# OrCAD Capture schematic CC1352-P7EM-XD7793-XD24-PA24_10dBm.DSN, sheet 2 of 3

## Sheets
2 CC1352-P7EM-XD7793-XD24-PA24_10: size A3
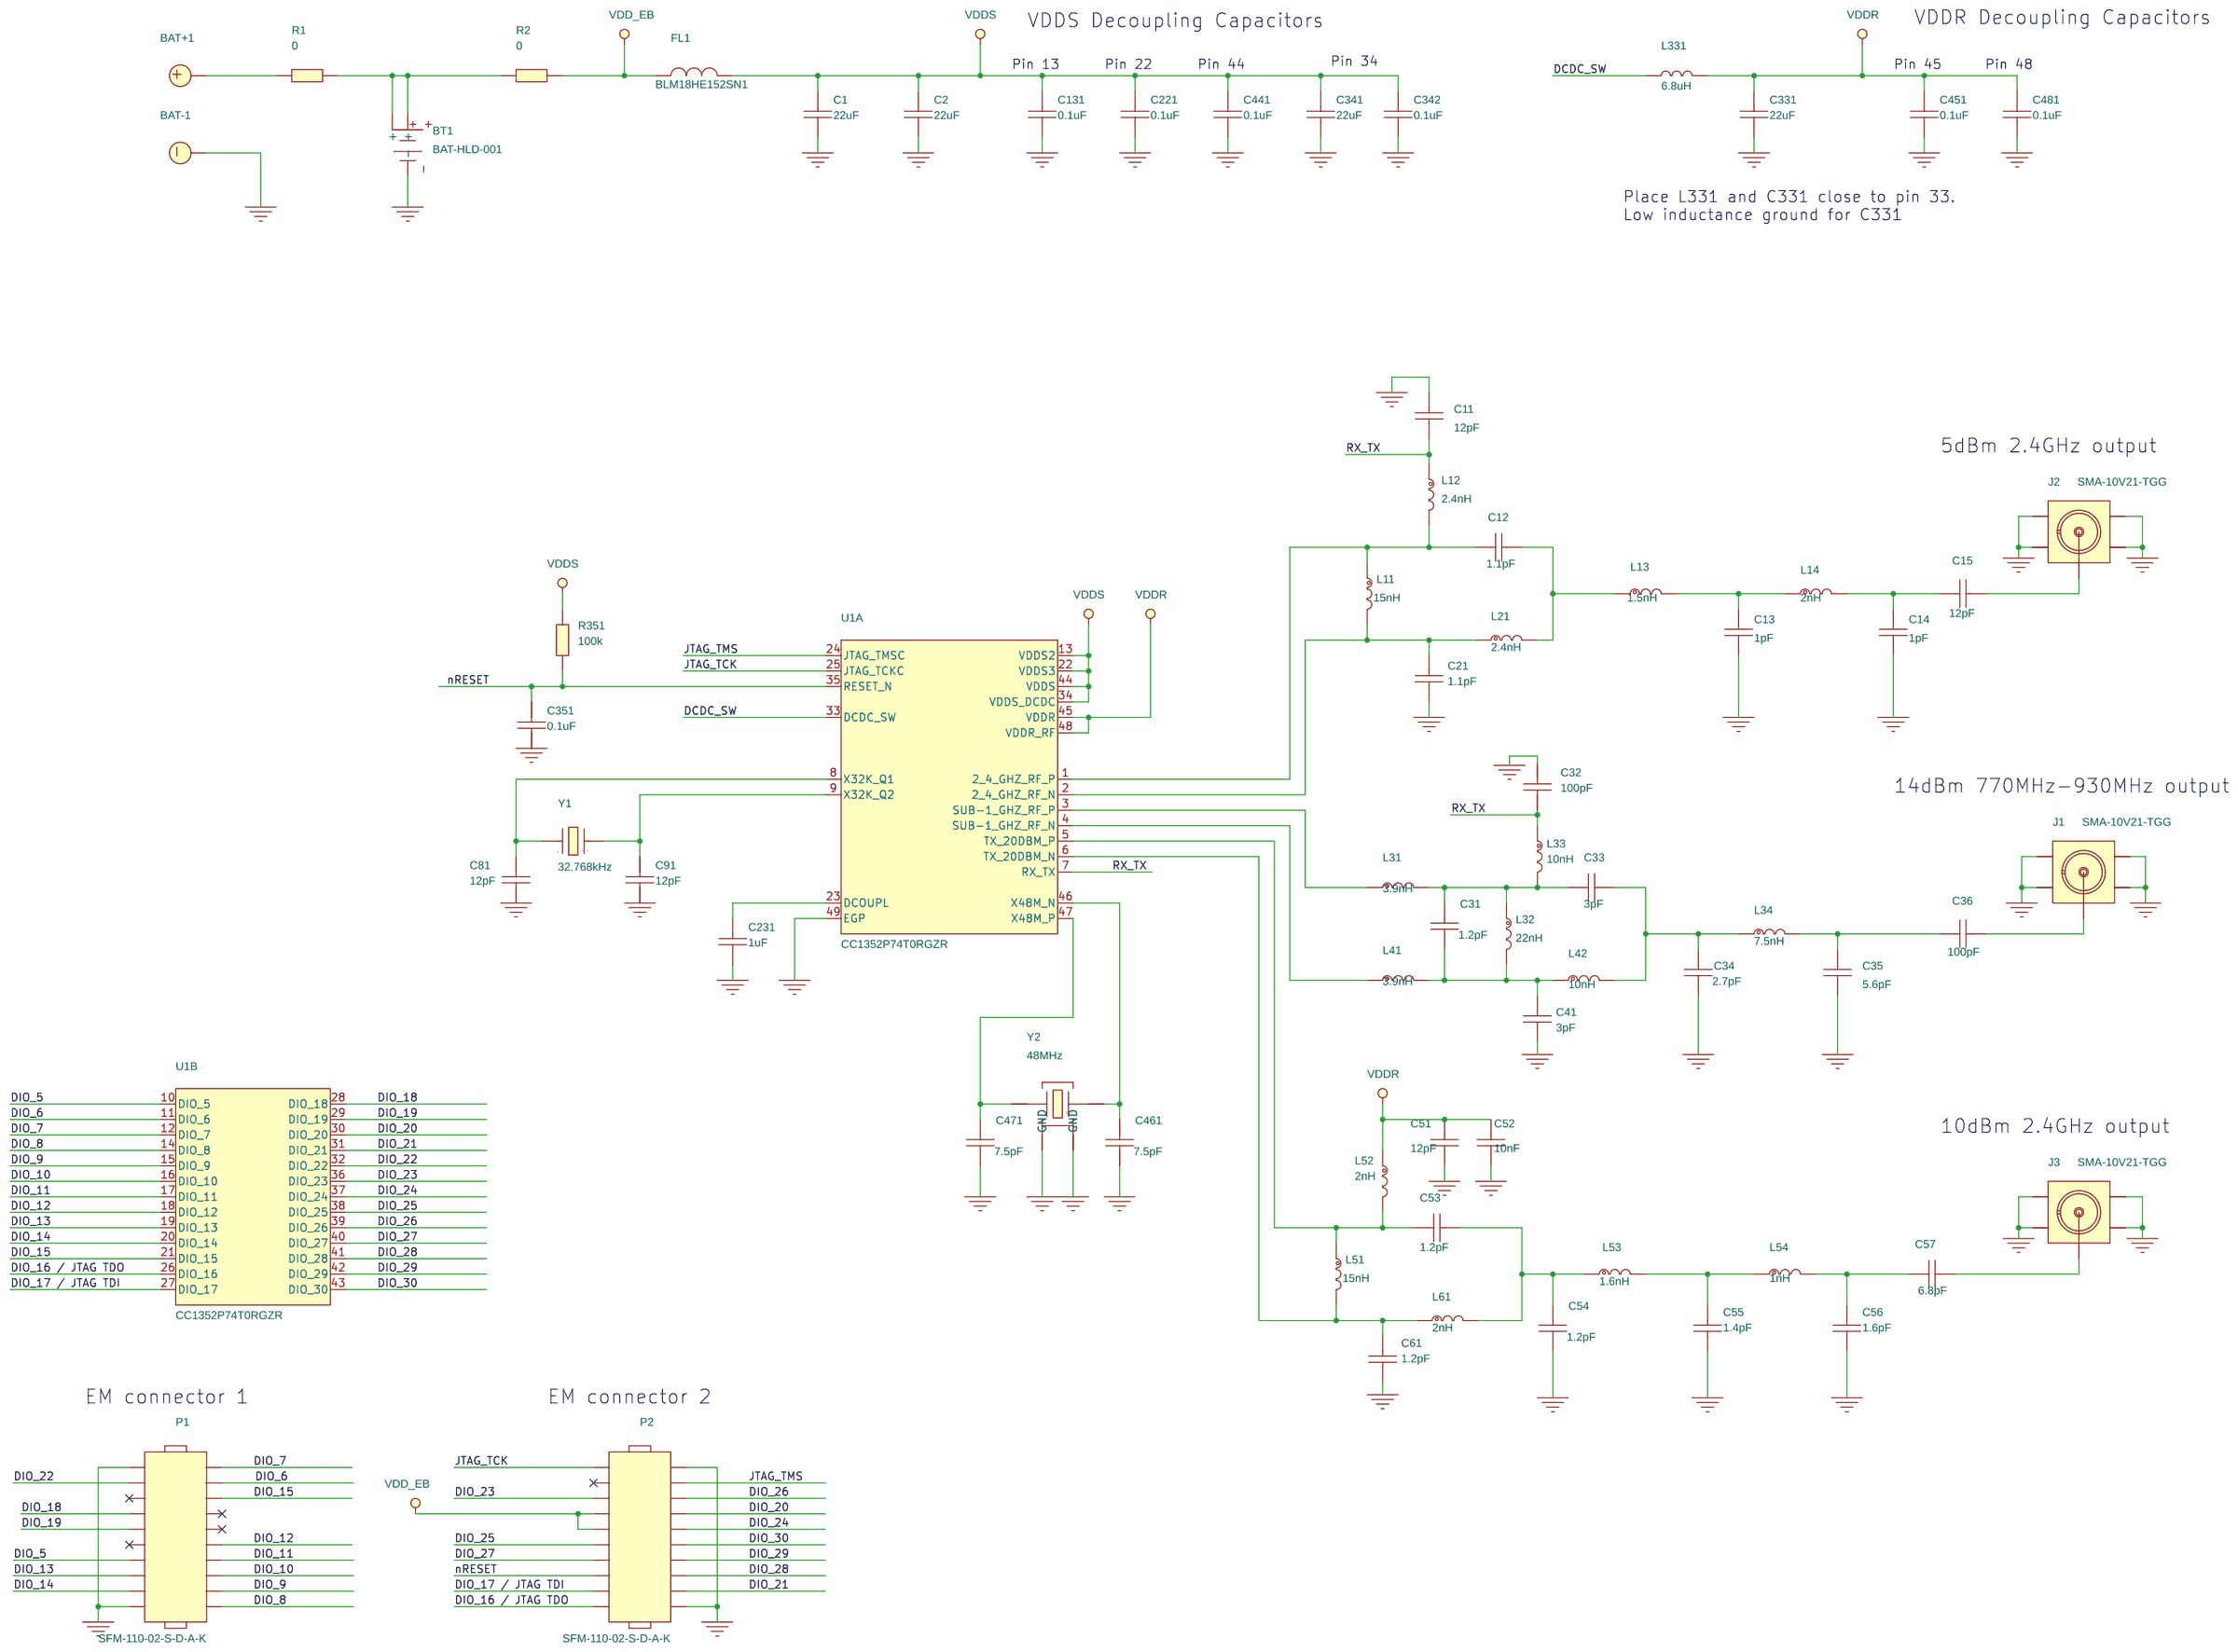
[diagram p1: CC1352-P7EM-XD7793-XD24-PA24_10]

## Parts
BAT+1  BAT+  [PAD_S2000OBL3600_1000M3000]
BAT-1  BAT-  [PAD_S2000OBL3600_1000M3000]
BT1  BAT-HLD-001  [BAT_BATHLD001N]
C1  22uF  [CAPC1608X100A2N]
C2  22uF  [CAPC1608X100A2N]
C11  12pF  [CAPC1005X60B2N]
C12  1.1pF  [CAPC1005X60B2N]
C13  1pF  [CAPC1005X60B2N]
C14  1pF  [CAPC1005X60B2N]
C15  12pF  [CAPC1005X60B2N]
C21  1.1pF  [CAPC1005X60B2N]
C31  1.2pF  [CAPC1005X60B2N]
C32  100pF  [CAPC1005X60B2N]
C33  3pF  [CAPC1005X60B2N]
C34  2.7pF  [CAPC1005X60B2N]
C35  5.6pF  [CAPC1005X60B2N]
C36  100pF  [CAPC1005X60B2N]
C41  3pF  [CAPC1005X60B2N]
C51  12pF  [CAPC1005X60B2N]
C52  10nF  [CAPC1005X60B2N]
C53  1.2pF  [CAPC1005X60B2N]
C54  1.2pF  [CAPC1005X60B2N]
C55  1.4pF  [CAPC1005X60B2N]
C56  1.6pF  [CAPC1005X60B2N]
C57  6.8pF  [CAPC1005X60B2N]
C61  1.2pF  [CAPC1005X60B2N]
C81  12pF  [CAPC1005X60B2N]
C91  12pF  [CAPC1005X60B2N]
C131  0.1uF  [CAPC1005X60B2N]
C221  0.1uF  [CAPC1005X60B2N]
C231  1uF  [CAPC1005X60B2N]
C331  22uF  [CAPC1608X100A2N]
C341  22uF  [CAPC1608X100A2N]
C342  0.1uF  [CAPC1005X60B2N]
C351  0.1uF  [CAPC1005X60B2N]
C441  0.1uF  [CAPC1005X60B2N]
C451  0.1uF  [CAPC1005X60B2N]
C461  7.5pF  [CAPC1005X60B2N]
C471  7.5pF  [CAPC1005X60B2N]
C481  0.1uF  [CAPC1005X60B2N]
FL1  BLM18HE152SN1  [FIL_BLM18HE152SN1DN]
J1  SMA-10V21-TGG  [HUSTSAN_SMA10V21TGGAN]
J2  SMA-10V21-TGG  [HUSTSAN_SMA10V21TGGAN]
J3  SMA-10V21-TGG  [HUSTSAN_SMA10V21TGGAN]
L11  15nH  [INDC1005X60D2N]
L12  2.4nH  [INDC1005X60D2N]
L13  1.5nH  [INDC1005X60D2N]
L14  2nH  [INDC1005X60D2N]
L21  2.4nH  [INDC1005X60D2N]
L31  3.9nH  [INDC1005X60D2N]
L32  22nH  [INDC1005X60D2N]
L33  10nH  [INDC1005X60D2N]
L34  7.5nH  [INDC1005X60D2N]
L41  3.9nH  [INDC1005X60D2N]
L42  10nH  [INDC1005X60D2N]
L51  15nH  [INDC1005X60D2N]
L52  2nH  [INDC1005X60D2N]
L53  1.6nH  [INDC1005X60D2N]
L54  1nH  [INDC1005X60D2N]
L61  2nH  [INDC1005X60D2N]
L331  6.8uH  [INDC2012X150A2N]
P1  SFM-110-02-S-D-A-K  [SAMTEC_SFM11002AN]
P2  SFM-110-02-S-D-A-K  [SAMTEC_SFM11002AN]
R1  0  [RESC1608X55A2N]
R2  0  [RESC1608X55A2N]
R351  100k  [RESC1005X40B2N]
U1  CC1352P74T0RGZR  [QFNFC50P700X700X100-49A2N]  (sections A,B)
Y1  32.768kHz  [XTAL_TZ1166C_B2N]
Y2  48MHz  [OSCCC200X160X50-4A2N]

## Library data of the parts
BAT+1 = BAT+: NON COMPONENT, BATTERY + PAD, SMD; Additional Datasheet URL: N/A; AutoDoc File: https://notefied-dynamic-precision.com/NotefiedWebServices/AutoDocs.aspx?itemid=87841; CLASS: IC; Country of Origin: Missing Info; Datasheet URL: N/A; Mass: N/A; Mounting Type: SMD; NOTEfied URL: https://notefied-dynamic-precision.com/NOTEfiedWebInterface/part/show?partNumber=19-00356; Packing Size: N/A; Packing Type: Missing Info; Part Number: 19-00356; Part Type: Non Component|PAD; ROHS: Missing Info; Revision: R016; Status: Released; Texas Part Status: Under Review; Type: Non Component; Vendor: NON_COMPONENT; Vendor Part Number: BATTERY - PAD; Vendor Part Status: Active
BAT-1 = BAT-: NON COMPONENT, BATTERY - PAD, SMD; Additional Datasheet URL: N/A; AutoDoc File: https://notefied-dynamic-precision.com/NotefiedWebServices/AutoDocs.aspx?itemid=87842; CLASS: IC; Country of Origin: Missing Info; Datasheet URL: N/A; Mass: N/A; Mounting Type: SMD; NOTEfied URL: https://notefied-dynamic-precision.com/NOTEfiedWebInterface/part/show?partNumber=19-00357; Packing Size: N/A; Packing Type: Missing Info; Part Number: 19-00357; Part Type: Non Component|PAD; ROHS: Missing Info; Revision: R016; Status: Released; Texas Part Status: Under Review; Type: Non Component; Vendor: NON_COMPONENT; Vendor Part Number: BATTERY - PAD; Vendor Part Status: Active
BT1 = BATT_3PINS: BATTERY, HOLDER, CR2032 AND CR2025 BATTERIES, SMD; ALT_SYMBOLS: BAT_BATHLD001L,BAT_BATHLD001M,BAT_BATHLD001AL,BAT_BATHLD001AM; Additional Datasheet URL: https://linxtechnologies.com/wp/wp-content/uploads/bat-hld-001.pdf; Budgetary Price: 0.211 USD; Country of Origin: Missing Info; Datasheet URL: https://linxtechnologies.com/wp/wp-content/uploads/battery_holder_overview_guide.pdf; FPLIST: BAT_BATHLD001N,BAT_BATHLD001AN; Lead Time: 6; Mass: N/A; Maximum Operating Temperature: N/A; Minimum Operating Temperature: N/A; NOTEfied URL: https://notefied-dynamic-precision.com/NOTEfiedWebInterface/part/show?partNumber=10-00027; Packing Size: 100; Packing Type: Bulk; Part Number: 10-00027; Part Type: Battery|HOLDER; REACH/SVHC Compliance: Compliant; REACH/SVHC Details: SVHC List Version Jun 20, 2016; REACH/SVHC Source: REACH Declaration; REACH/SVHC Status: Unaffected; ROHS: Compliant; Revision: R019; Status: Released; Texas Part Status: Under Review; Type: Battery; Vendor: LINX; Vendor Part Status: Active
C1 C2 C331 C341 = CAPACITOR: CAPACITOR, CERAMIC X6S, 22uF, 6.3V, -20%/+20%, -55DEGC/+105DEGC, 0603, SMD; ALT_SYMBOLS: CAPC1608X100A2L,CAPC1608X100A2M; Additional Datasheet URL: https://search.murata.co.jp/Ceramy/image/img/A01X/G101/ENG/GRM188C80J226ME15-02A.pdf; AutoDoc File: https://notefied-dynamic-precision.com/DB/Apps/Desktop/Item/Object.aspx?id=104385; BU Name: DYNAMIC PRECISION GDANSK; Budget Currency: EUR; Budget Price: 0.062; Budgetary Price: 0.07648 USD; Client Status: UNDER_REVIEW; Datasheet URL: https://www.murata.com/-/media/webrenewal/support/library/catalog/products/capacitor/mlcc/c02e.ashx; Datasheet URL 1: http://psearch.murata.com/capacitor/product/GRM188R60J226MEA0%23.pdf; Datasheet URL 2: http://search.murata.co.jp/Ceramy/image/img/w_hinm/L0005E.pdf; Definied Quality: INDUSTRIAL; Dielectric Type: X6S; Esd Level: N/A; Lead Time: 15; LifeCycle Status: ACTIVE; MPN: GRM188R60J226MEA0D; MPN Status: ACTIVE; Manufacturer: MURATA; Mass: 0.0091g; Max Oper Temp: +85DEGC; Max Tol: +20%; Maximum Operating Temperature: +105DEGC; Maximum Tolerance: +20%; Min Oper Temp: -55DEGC; Min Tol: -20%; Minimum Operating Temperature: -55DEGC; Minimum Tolerance: -20%; Mounting Type: SMD; NOTE Status: PREFERRED; NOTEfied URL: https://notefied-dynamic-precision.com/NOTEfiedWebInterface/part/show?partNumber=02-09737; PCB Package: 0603; Packing Size: 4000; Packing Type: Tape & Reel; Part Number: 02-09737; Part Type: Capacitor|CERAMIC|0603|STANDARD; REACH/SVHC Compliance: Compliant; REACH/SVHC Details: SVHC List Version Jan 16, 2020; REACH/SVHC Source: REACH Declaration; REACH/SVHC Status: Unaffected; REACH/SVHC_COMPLIANCE: COMPLIANT; REACH/SVHC_DETAILS: SVHC LIST VERSION Dec 17, 2015; REACH/SVHC_SOURCE: REACH DECLARATION; REACH/SVHC_STATUS: UNAFFECTED; ROHS: Compliant; Rated Current: N/A; Rated Voltage: 6.3V; Revision: R001; RoHS Status: ROHS_COMPLIANT; Rtd Voltage: 6.3V; Status: Released; Texas Part Status: Under Review; Type: Capacitor; Vendor: MURATA; Vendor Part Number: GRM188C80J226ME15D; Vendor Part Status: Active; WEIGHT: 0.0091g
C11 C15 C51 = CAPACITOR: CAPACITOR, CERAMIC C0G/NP0, 12pF, 50V, -5%/+5%, -55DEGC/+125DEGC, 0402, SMD; Additional Datasheet URL: https://search.murata.co.jp/Ceramy/image/img/A01X/G101/ENG/GJM1555C1H120JB01-01.pdf; AutoDoc File: https://notefied-dynamic-precision.com/DB/Apps/Desktop/Item/Object.aspx?id=113345; BU Name: TEXAS INSTRUMENTS NORWAY; Budget Currency: EUR; Budget Price: 0.007; Datasheet URL: https://www.murata.com/-/media/webrenewal/support/library/catalog/products/capacitor/mlcc/c02e.ashx; Datasheet URL 1: http://psearch.murata.com/capacitor/product/GRM1555C1H120JA01%23.pdf; Datasheet URL 2: http://search.murata.co.jp/Ceramy/image/img/w_hinm/L0005E.pdf; Dielectric Type: C0G/NP0; Mass: 0.0016g; Max Oper Temp: +125DEGC; Max Tol: +5%; Maximum Operating Temperature: +125DEGC; Maximum Tolerance: +5%; Min Oper Temp: -55DEGC; Min Tol: -5%; Minimum Operating Temperature: -55DEGC; Minimum Tolerance: -5%; Mounting Type: SMD; NOTEfied URL: https://notefied-dynamic-precision.com/NOTEfiedWebInterface/part/show?partNumber=02-09704; PCB Package: 0402; Packing Size: 10000; Packing Type: Tape & Reel; Part Number: 02-09704; Part Type: Capacitor|CERAMIC|0402|STANDARD; REACH/SVHC Compliance: Compliant; REACH/SVHC Details: SVHC List Version Jan 16, 2020; REACH/SVHC Source: REACH Declaration; REACH/SVHC Status: Unaffected; REACH/SVHC_COMPLIANCE: COMPLIANT; REACH/SVHC_DETAILS: SVHC LIST VERSION Dec 17, 2015; REACH/SVHC_SOURCE: REACH DECLARATION; REACH/SVHC_STATUS: UNAFFECTED; ROHS: Compliant; Rated Voltage: 50V; Revision: R002; RoHS Status: ROHS_COMPLIANT; Rtd Voltage: 50V; Status: Released; Texas Part Status: Under Review; Type: Capacitor; Vendor: MURATA; Vendor Part Number: GJM1555C1H120JB01D; Vendor Part Status: Active; Weight: 0.0016g
C12 C21 = CAPACITOR: CAPACITOR, CERAMIC C0G/NP0, 1.1pF, 50V, -0.1pF/+0.1pF, -55DEGC/+125DEGC, 0402, SMD; Additional Datasheet URL: https://search.murata.co.jp/Ceramy/image/img/A01X/G101/ENG/GJM1555C1H1R1BB01-01.pdf; AutoDoc File: https://notefied-dynamic-precision.com/DB/Apps/Desktop/Item/Object.aspx?id=116030; BU Name: TEXAS INSTRUMENTS NORWAY; Budget Currency: EUR; Budget Price: 0.011; Client Status: UNDER_REVIEW; Datasheet URL: https://www.murata.com/-/media/webrenewal/support/library/catalog/products/capacitor/mlcc/c02e.ashx; Datasheet URL 1: http://psearch.murata.com/capacitor/product/GRM1555C1H1R1BA01%23.pdf; Datasheet URL 2: http://search.murata.co.jp/Ceramy/image/img/w_hinm/L0005E.pdf; Dielectric Type: C0G/NP0; Mass: 0.0016g; Max Oper Temp: +125DEGC; Max Tol: +0.1pF; Maximum Operating Temperature: +125DEGC; Maximum Tolerance: +0.1pF; Min Oper Temp: -55DEGC; Min Tol: -0.1pF; Minimum Operating Temperature: -55DEGC; Minimum Tolerance: -0.1pF; Mounting Type: SMD; NOTEfied URL: https://notefied-dynamic-precision.com/NOTEfiedWebInterface/part/show?partNumber=02-09708; PCB Package: 0402; Packing Size: 10000; Packing Type: Tape & Reel; Part Number: 02-09708; Part Type: Capacitor|CERAMIC|0402|STANDARD; REACH/SVHC Compliance: Compliant; REACH/SVHC Details: SVHC List Version Jan 16, 2020; REACH/SVHC Source: REACH Declaration; REACH/SVHC Status: Unaffected; REACH/SVHC_COMPLIANCE: COMPLIANT; REACH/SVHC_DETAILS: SVHC LIST VERSION Jun 20, 2016; REACH/SVHC_SOURCE: REACH DECLARATION; REACH/SVHC_STATUS: UNAFFECTED; ROHS: Compliant; Rated Voltage: 50V; Revision: R002; RoHS Status: ROHS_COMPLIANT; Rtd Voltage: 50V; Status: Released; Texas Part Status: Under Review; Type: Capacitor; Vendor: MURATA; Vendor Part Number: GJM1555C1H1R1BB01D; Vendor Part Status: Active; Weight: 0.0016g
C13 C14 = CAPACITOR: CAPACITOR, CERAMIC C0G/NP0, 1pF, 50V, -0.1pF/+0.1pF, -55DEGC/+125DEGC, 0402, SMD; Additional Datasheet URL: https://search.murata.co.jp/Ceramy/image/img/A01X/G101/ENG/GJM1555C1H1R0BB01-01.pdf; AutoDoc File: https://notefied-dynamic-precision.com/DB/Apps/Desktop/Item/Object.aspx?id=116031; BU Name: TEXAS INSTRUMENTS NORWAY; Budget Currency: EUR; Budget Price: 0.011; Client Status: UNDER_REVIEW; Datasheet URL: https://www.murata.com/-/media/webrenewal/support/library/catalog/products/capacitor/mlcc/c02e.ashx; Datasheet URL 1: http://psearch.murata.com/capacitor/product/GRM1555C1H1R0BA01%23.pdf; Datasheet URL 2: http://search.murata.co.jp/Ceramy/image/img/w_hinm/L0005E.pdf; Dielectric Type: C0G/NP0; Mass: 0.0016g; Max Oper Temp: +125DEGC; Max Tol: +0.1pF; Maximum Operating Temperature: +125DEGC; Maximum Tolerance: +0.1pF; Min Oper Temp: -55DEGC; Min Tol: -0.1pF; Minimum Operating Temperature: -55DEGC; Minimum Tolerance: -0.1pF; Mounting Type: SMD; NOTEfied URL: https://notefied-dynamic-precision.com/NOTEfiedWebInterface/part/show?partNumber=02-09705; PCB Package: 0402; Packing Size: 10000; Packing Type: Tape & Reel; Part Number: 02-09705; Part Type: Capacitor|CERAMIC|0402|STANDARD; REACH/SVHC Compliance: Compliant; REACH/SVHC Details: SVHC List Version Jan 16, 2020; REACH/SVHC Source: REACH Declaration; REACH/SVHC Status: Unaffected; REACH/SVHC_COMPLIANCE: COMPLIANT; REACH/SVHC_DETAILS: SVHC LIST VERSION Dec 17, 2015; REACH/SVHC_SOURCE: REACH DECLARATION; REACH/SVHC_STATUS: UNAFFECTED; ROHS: Compliant; Rated Voltage: 50V; Revision: R002; RoHS Status: ROHS_COMPLIANT; Rtd Voltage: 50V; Status: Released; Texas Part Status: Under Review; Type: Capacitor; Vendor: MURATA; Vendor Part Number: GJM1555C1H1R0BB01D; Vendor Part Status: Active; Weight: 0.0016g
C31 C54 = CAPACITOR: CAPACITOR, CERAMIC C0G/NP0, 1.2pF, 50V, -0.1pF/+0.1pF, -55DEGC/+125DEGC, 0402, SMD; Additional Datasheet URL: https://search.murata.co.jp/Ceramy/image/img/A01X/G101/ENG/GJM1555C1H1R2BB01-01.pdf; Datasheet URL: https://www.murata.com/-/media/webrenewal/support/library/catalog/products/capacitor/mlcc/c02e.ashx; Dielectric Type: C0G/NP0; Mass: 0.0016g; Maximum Operating Temperature: +125DEGC; Maximum Tolerance: +0.1pF; Minimum Operating Temperature: -55DEGC; Minimum Tolerance: -0.1pF; Mounting Type: SMD; NOTEfied URL: https://notefied-dynamic-precision.com/NOTEfiedWebInterface/part/show?partNumber=02-09709; PCB Package: 0402; Packing Size: 10000; Packing Type: Tape & Reel; Part Number: 02-09709; Part Type: Capacitor|CERAMIC|0402|STANDARD; REACH/SVHC Compliance: Compliant; REACH/SVHC Details: SVHC List Version Jan 16, 2020; REACH/SVHC Source: REACH Declaration; REACH/SVHC Status: Unaffected; ROHS: Compliant; Rated Voltage: 50V; Revision: R002; Status: Released; Texas Part Status: Under Review; Type: Capacitor; Vendor: MURATA; Vendor Part Number: GJM1555C1H1R2BB01D; Vendor Part Status: Active
C32 C36 = CAPACITOR: CAPACITOR, CERAMIC C0G/NP0, 100pF, 50V, -5%/+5%, -55DEGC/+125DEGC, 0402, SMD; Additional Datasheet URL: https://search.murata.co.jp/Ceramy/image/img/A01X/G101/ENG/GRT1555C1H101JA02-01.pdf; AutoDoc File: https://notefied-dynamic-precision.com/DB/Apps/Desktop/Item/Object.aspx?id=113347; BU Name: TEXAS INSTRUMENTS NORWAY; Budget Currency: EUR; Budget Price: 0.004; Budgetary Price: 0.023 EUR; Datasheet URL: https://www.murata.com/-/media/webrenewal/support/library/catalog/products/capacitor/mlcc/c02e.ashx?la=en-gb; Datasheet URL 1: http://psearch.murata.com/capacitor/product/GRM1555C1H101JA01%23.pdf; Datasheet URL 2: http://search.murata.co.jp/Ceramy/image/img/w_hinm/L0005E.pdf; Definied Quality: INDUSTRIAL; Dielectric Type: C0G/NP0; Esd Level: N/A; Lead Time: 19; MPN: GRM1555C1H101JA01D; MPN Status: ACTIVE; MSL: 1; MTBF: N/A; MTBF Standard: N/A; Manufacturer: MURATA; Mass: 0.0016g; Max Oper Temp: +125DEGC; Max Tol: +5%; Maximum Operating Temperature: +125DEGC; Maximum Tolerance: +5%; Min Oper Temp: -55DEGC; Min Tol: -5%; Minimum Operating Temperature: -55DEGC; Minimum Tolerance: -5%; Mounting Type: SMD; NOTE Status: PREFERRED; NOTEfied URL: https://notefied-dynamic-precision.com/NOTEfiedWebInterface/part/show?partNumber=02-09727; Old Footprint: CAPC1005X60N; PCB Package: 0402; Packing Size: 10000; Packing Type: Tape & Reel; Part Number: 02-09727; Part Type: Capacitor|CERAMIC|0402|STANDARD; REACH/SVHC Compliance: Compliant; REACH/SVHC Details: SVHC List Version Jan 16, 2020; REACH/SVHC Source: REACH Declaration; REACH/SVHC Status: Unaffected; REACH/SVHC_COMPLIANCE: COMPLIANT; REACH/SVHC_DETAILS: SVHC LIST VERSION Dec 17, 2015; REACH/SVHC_SOURCE: REACH DECLARATION; REACH/SVHC_STATUS: UNAFFECTED; ROHS: Compliant; Rated Voltage: 50V; Revision: R002; RoHS Status: ROHS_COMPLIANT; Rtd Voltage: 50V; Status: Released; Texas Part Status: Under Review; Type: Capacitor; Vendor: MURATA; Vendor Part Number: GRT1555C1H101JA02D; Vendor Part Status: Active; WEIGHT: 0.0016g
C33 C41 = CAPACITOR: CAPACITOR, CERAMIC C0G/NP0, 3pF, 50V, -0.25pF/+0.25pF, -55DEGC/+125DEGC, 0402, SMD; Additional Datasheet URL: https://search.murata.co.jp/Ceramy/image/img/A01X/G101/ENG/GJM1555C1H3R0CB01-01.pdf; AutoDoc File: https://notefied-dynamic-precision.com/DB/Apps/Desktop/Item/Object.aspx?id=113359; BU Name: TEXAS INSTRUMENTS NORWAY; Budget Currency: EUR; Budget Price: 0.006; Datasheet URL: https://www.murata.com/-/media/webrenewal/support/library/catalog/products/capacitor/mlcc/c02e.ashx; Datasheet URL 1: http://psearch.murata.com/capacitor/product/GRM1555C1H3R6CA01%23.pdf; Datasheet URL 2: http://search.murata.co.jp/Ceramy/image/img/w_hinm/L0005E.pdf; Dielectric Type: C0G/NP0; MPN: GRM1555C1H3R6CA01D; MPN Status: ACTIVE; Manufacturer: MURATA; Mass: 0.0016g; Max Oper Temp: +125DEGC; Max Tol: +0.25pF; Maximum Operating Temperature: +125DEGC; Maximum Tolerance: +0.25pF; Min Oper Temp: -55DEGC; Min Tol: -0.25pF; Minimum Operating Temperature: -55DEGC; Minimum Tolerance: -0.25pF; Mounting Type: SMD; NOTE Status: PREFERRED; NOTEfied URL: https://notefied-dynamic-precision.com/NOTEfiedWebInterface/part/show?partNumber=02-09713; Old Footprint: CAPC1005X60N; PCB Package: 0402; Packing Size: 10000; Packing Type: Tape & Reel; Part Number: 02-09713; Part Type: Capacitor|CERAMIC|0402|STANDARD; REACH/SVHC Compliance: Compliant; REACH/SVHC Details: SVHC List Version Jan 16, 2020; REACH/SVHC Source: REACH Declaration; REACH/SVHC Status: Unaffected; REACH/SVHC_COMPLIANCE: COMPLIANT; REACH/SVHC_DETAILS: SVHC LIST VERSION Jun 20, 2016; REACH/SVHC_SOURCE: REACH DECLARATION; REACH/SVHC_STATUS: UNAFFECTED; ROHS: Compliant; Rated Voltage: 50V; Revision: R002; RoHS Status: ROHS_COMPLIANT; Rtd Voltage: 50V; Status: Released; Texas Part Status: Under Review; Type: Capacitor; Vendor: MURATA; Vendor Part Number: GJM1555C1H3R0CB01D; Vendor Part Status: Active; Weight: 0.0016g
C34 = CAPACITOR: CAPACITOR, CERAMIC C0G/NP0, 2.7pF, 50V, -0.25pF/+0.25pF, -55DEGC/+125DEGC, 0402, SMD; Additional Datasheet URL: https://search.murata.co.jp/Ceramy/image/img/A01X/G101/ENG/GJM1555C1H2R7CB01-01.pdf; AutoDoc File: https://notefied-dynamic-precision.com/DB/Apps/Desktop/Item/Object.aspx?id=113356; BU Name: TEXAS INSTRUMENTS NORWAY; Budget Currency: EUR; Budget Price: 0.007; Datasheet URL: https://www.murata.com/-/media/webrenewal/support/library/catalog/products/capacitor/mlcc/c02e.ashx; Datasheet URL 1: http://psearch.murata.com/capacitor/product/GRM1555C1H2R7CA01%23.pdf; Datasheet URL 2: http://search.murata.co.jp/Ceramy/image/img/w_hinm/L0005E.pdf; Definied Quality: INDUSTRIAL; Dielectric Type: C0G/NP0; Esd Level: N/A; MPN: GRM1555C1H2R7CA01D; MPN Status: ACTIVE; MSL: 1; MTBF: N/A; MTBF Standard: N/A; Manufacturer: MURATA; Mass: 0.0016g; Max Oper Temp: +125DEGC; Max Tol: +0.25pF; Maximum Operating Temperature: +125DEGC; Maximum Tolerance: +0.25pF; Min Oper Temp: -55DEGC; Min Tol: -0.25pF; Minimum Operating Temperature: -55DEGC; Minimum Tolerance: -0.25pF; Mounting Type: SMD; NOTE Status: PREFERRED; NOTEfied URL: https://notefied-dynamic-precision.com/NOTEfiedWebInterface/part/show?partNumber=02-09712; Old Footprint: CAPC1005X60N; PCB Package: 0402; Packing Size: 10000; Packing Type: Tape & Reel; Part Number: 02-09712; Part Type: Capacitor|CERAMIC|0402|STANDARD; REACH/SVHC Compliance: Compliant; REACH/SVHC Details: SVHC List Version Jan 16, 2020; REACH/SVHC Source: REACH Declaration; REACH/SVHC Status: Unaffected; REACH/SVHC_COMPLIANCE: COMPLIANT; REACH/SVHC_DETAILS: SVHC LIST VERSION Dec 17, 2015; REACH/SVHC_SOURCE: REACH DECLARATION; REACH/SVHC_STATUS: UNAFFECTED; ROHS: Compliant; Rated Voltage: 50V; Revision: R002; RoHS Status: ROHS_COMPLIANT; Rtd Voltage: 50V; Status: Released; Texas Part Status: Under Review; Type: Capacitor; Vendor: MURATA; Vendor Part Number: GJM1555C1H2R7CB01D; Vendor Part Status: Active; WEIGHT: 0.0016g
C35 = CAPACITOR: CAPACITOR, CERAMIC C0G/NP0, 5.6pF, 50V, -0.25pF/+0.25pF, -55DEGC/+125DEGC, 0402, SMD; Additional Datasheet URL: https://search.murata.co.jp/Ceramy/image/img/A01X/G101/ENG/GJM1555C1H5R6CB01-01.pdf; AutoDoc File: https://notefied-dynamic-precision.com/DB/Apps/Desktop/Item/Object.aspx?id=113354; BU Name: TEXAS INSTRUMENTS NORWAY; Budget Currency: EUR; Budget Price: 0.007; Datasheet URL: https://www.murata.com/-/media/webrenewal/support/library/catalog/products/capacitor/mlcc/c02e.ashx; Datasheet URL 1: http://psearch.murata.com/capacitor/product/GRM1555C1H6R2CA01%23.pdf; Datasheet URL 2: http://search.murata.co.jp/Ceramy/image/img/w_hinm/L0005E.pdf; Definied Quality: INDUSTRIAL; Dielectric Type: C0G/NP0; Esd Level: N/A; MPN: GRM1555C1H6R2CA01D; MPN Status: ACTIVE; MSL: 1; MTBF: N/A; MTBF Standard: N/A; Manufacturer: MURATA; Mass: 0.0016g; Max Oper Temp: +125DEGC; Max Tol: +0.25pF; Maximum Operating Temperature: +125DEGC; Maximum Tolerance: +0.25pF; Min Oper Temp: -55DEGC; Min Tol: -0.25pF; Minimum Operating Temperature: -55DEGC; Minimum Tolerance: -0.25pF; Mounting Type: SMD; NOTE Status: PREFERRED; NOTEfied URL: https://notefied-dynamic-precision.com/NOTEfiedWebInterface/part/show?partNumber=02-09716; Old Footprint: CAPC1005X60N; PCB Package: 0402; Packing Size: 10000; Packing Type: Tape & Reel; Part Number: 02-09716; Part Type: Capacitor|CERAMIC|0402|STANDARD; REACH/SVHC Compliance: Compliant; REACH/SVHC Details: SVHC List Version Jan 16, 2020; REACH/SVHC Source: REACH Declaration; REACH/SVHC Status: Unaffected; REACH/SVHC_COMPLIANCE: COMPLIANT; REACH/SVHC_DETAILS: SVHC LIST VERSION Dec 17, 2015; REACH/SVHC_SOURCE: REACH DECLARATION; REACH/SVHC_STATUS: UNAFFECTED; ROHS: Compliant; Rated Voltage: 50V; Revision: R002; RoHS Status: ROHS_COMPLIANT; Rtd Voltage: 50V; Status: Released; Texas Part Status: Under Review; Type: Capacitor; Vendor: MURATA; Vendor Part Number: GJM1555C1H5R6CB01D; Vendor Part Status: Active; WEIGHT: 0.0016g
C52 = CAPACITOR: CAPACITOR, CERAMIC X7R, 10nF, 50V, -20%/+20%, -55DEGC/+125DEGC, 0402, SMD; Additional Datasheet URL: https://search.murata.co.jp/Ceramy/image/img/A01X/G101/ENG/GRM155R71H103MA88-01A.pdf; AutoDoc File: https://notefied-dynamic-precision.com/DB/Apps/Desktop/Item/Object.aspx?id=114570; BU Name: TEXAS INSTRUMENTS NORWAY; Budget Currency: EUR; Budget Price: 0.003; Client Status: UNDER_REVIEW; Datasheet URL: https://www.murata.com/-/media/webrenewal/support/library/catalog/products/capacitor/mlcc/c02e.ashx; Datasheet URL 1: http://psearch.murata.com/capacitor/product/GRM155R71E103KA01%23.pdf; Datasheet URL 2: http://search.murata.co.jp/Ceramy/image/img/w_hinm/L0005E.pdf; Dielectric Type: X7R; Mass: 0.0016g; Max Oper Temp: +125DEGC; Max Tol: +10%; Maximum Operating Temperature: +125DEGC; Maximum Tolerance: +20%; Min Oper Temp: -55DEGC; Min Tol: -10%; Minimum Operating Temperature: -55DEGC; Minimum Tolerance: -20%; Mounting Type: SMD; NOTEfied URL: https://notefied-dynamic-precision.com/NOTEfiedWebInterface/part/show?partNumber=02-09722; PCB Package: 0402; Packing Size: 10000; Packing Type: Tape & Reel; Part Number: 02-09722; Part Type: Capacitor|CERAMIC|0402|STANDARD; REACH/SVHC Compliance: Compliant; REACH/SVHC Details: SVHC List Version Jan 16, 2020; REACH/SVHC Source: REACH Declaration; REACH/SVHC Status: Unaffected; REACH/SVHC_COMPLIANCE: COMPLIANT; REACH/SVHC_DETAILS: SVHC LIST VERSION Jun 20, 2016; REACH/SVHC_SOURCE: REACH DECLARATION; REACH/SVHC_STATUS: UNAFFECTED; ROHS: Compliant; Rated Voltage: 50V; Revision: R002; RoHS Status: ROHS_COMPLIANT; Rtd Voltage: 25V; Status: Released; Texas Part Status: Under Review; Type: Capacitor; Vendor: MURATA; Vendor Part Number: GRM155R71H103MA88D; Vendor Part Status: Active; Weight: 0.0016g
C53 C61 = CAPACITOR: CAPACITOR, CERAMIC C0G/NP0, 1.2pF, 50V, -0.1pF/+0.1pF, -55DEGC/+125DEGC, 0402, SMD; Additional Datasheet URL: https://search.murata.co.jp/Ceramy/image/img/A01X/G101/ENG/GJM1555C1H1R2BB01-01.pdf; AutoDoc File: https://notefied-dynamic-precision.com/DB/Apps/Desktop/Item/Object.aspx?id=116143; BU Name: TEXAS INSTRUMENTS NORWAY; Budget Currency: EUR; Budget Price: 0.009; Client Status: UNDER_REVIEW; Datasheet URL: https://www.murata.com/-/media/webrenewal/support/library/catalog/products/capacitor/mlcc/c02e.ashx; Datasheet URL 1: http://psearch.murata.com/capacitor/product/GRM1555C1H1R2BA01%23.pdf; Datasheet URL 2: http://search.murata.co.jp/Ceramy/image/img/w_hinm/L0005E.pdf; Dielectric Type: C0G/NP0; Mass: 0.0016g; Max Oper Temp: +125DEGC; Max Tol: +0.1pF; Maximum Operating Temperature: +125DEGC; Maximum Tolerance: +0.1pF; Min Oper Temp: -55DEGC; Min Tol: -0.1pF; Minimum Operating Temperature: -55DEGC; Minimum Tolerance: -0.1pF; Mounting Type: SMD; NOTEfied URL: https://notefied-dynamic-precision.com/NOTEfiedWebInterface/part/show?partNumber=02-09709; PCB Package: 0402; Packing Size: 10000; Packing Type: Tape & Reel; Part Number: 02-09709; Part Type: Capacitor|CERAMIC|0402|STANDARD; REACH/SVHC Compliance: Compliant; REACH/SVHC Details: SVHC List Version Jan 16, 2020; REACH/SVHC Source: REACH Declaration; REACH/SVHC Status: Unaffected; REACH/SVHC_COMPLIANCE: COMPLIANT; REACH/SVHC_DETAILS: SVHC LIST VERSION Jun 20, 2016; REACH/SVHC_SOURCE: REACH DECLARATION; REACH/SVHC_STATUS: UNAFFECTED; ROHS: Compliant; Rated Voltage: 50V; Revision: R002; RoHS Status: ROHS_COMPLIANT; Rtd Voltage: 50V; Status: Released; Texas Part Status: Under Review; Type: Capacitor; Vendor: MURATA; Vendor Part Number: GJM1555C1H1R2BB01D; Vendor Part Status: Active; Weight: 0.0016g
C55 = CAPACITOR: CAPACITOR, CERAMIC C0G/NP0, 1.4pF, 50V, -0.1pF/+0.1pF, -55DEGC/+125DEGC, 0402, SMD; Additional Datasheet URL: https://search.murata.co.jp/Ceramy/image/img/A01X/G101/ENG/GJM1555C1H1R4BB01-01.pdf; AutoDoc File: https://notefied-dynamic-precision.com/DB/Apps/Desktop/Item/Object.aspx?id=116145; BU Name: TEXAS INSTRUMENTS NORWAY; Client Status: UNDER_REVIEW; Datasheet URL: https://www.murata.com/-/media/webrenewal/support/library/catalog/products/capacitor/mlcc/c02e.ashx; Datasheet URL 1: http://www.murata.com/~/media/webrenewal/support/library/catalog/products/capacitor/mlcc/c02e.ashx?la=en-gb; Datasheet URL 2: N/A; Dielectric Type: C0G/NP0; Mass: 0.0016g; Max Oper Temp: +125DEGC; Max Tol: +0.1pF; Maximum Operating Temperature: +125DEGC; Maximum Tolerance: +0.1pF; Min Oper Temp: -55DEGC; Min Tol: -0.1pF; Minimum Operating Temperature: -55DEGC; Minimum Tolerance: -0.1pF; Mounting Type: SMD; NOTEfied URL: https://notefied-dynamic-precision.com/NOTEfiedWebInterface/part/show?partNumber=02-10046; PCB Package: 0402; Packing Size: 10000; Packing Type: Tape & Reel; Part Number: 02-10046; Part Type: Capacitor|CERAMIC|0402|STANDARD; REACH/SVHC Compliance: Compliant; REACH/SVHC Details: SVHC List Version Jun 25, 2020; REACH/SVHC Source: REACH Declaration; REACH/SVHC Status: Unaffected; REACH/SVHC_COMPLIANCE: COMPLIANT; REACH/SVHC_DETAILS: SVHC LIST VERSION Jun 20, 2016; REACH/SVHC_SOURCE: REACH DECLARATION; REACH/SVHC_STATUS: UNAFFECTED; ROHS: Compliant; Rated Voltage: 50V; Revision: R001; RoHS Status: ROHS_COMPLIANT; Rtd Voltage: 50V; Status: Released; Texas Part Status: Under Review; Type: Capacitor; Vendor: MURATA; Vendor Part Number: GJM1555C1H1R4BB01D; Vendor Part Status: Active
C56 = CAPACITOR: CAPACITOR, CERAMIC C0G/NP0, 1.6pF, 50V, -0.1pF/+0.1pF, -55DEGC/+125DEGC, 0402, SMD; Additional Datasheet URL: https://search.murata.co.jp/Ceramy/image/img/A01X/G101/ENG/GJM1555C1H1R6BB01-01.pdf; AutoDoc File: https://notefied-dynamic-precision.com/DB/Apps/Desktop/Item/Object.aspx?id=116145; BU Name: TEXAS INSTRUMENTS NORWAY; Client Status: UNDER_REVIEW; Datasheet URL: https://www.murata.com/-/media/webrenewal/support/library/catalog/products/capacitor/mlcc/c02e.ashx; Datasheet URL 1: http://www.murata.com/~/media/webrenewal/support/library/catalog/products/capacitor/mlcc/c02e.ashx?la=en-gb; Datasheet URL 2: N/A; Dielectric Type: C0G/NP0; Mass: 0.0016g; Max Oper Temp: +125DEGC; Max Tol: +0.1pF; Maximum Operating Temperature: +125DEGC; Maximum Tolerance: +0.1pF; Min Oper Temp: -55DEGC; Min Tol: -0.1pF; Minimum Operating Temperature: -55DEGC; Minimum Tolerance: -0.1pF; Mounting Type: SMD; NOTEfied URL: https://notefied-dynamic-precision.com/NOTEfiedWebInterface/part/show?partNumber=02-09710; PCB Package: 0402; Packing Size: 10000; Packing Type: Tape & Reel; Part Number: 02-09710; Part Type: Capacitor|CERAMIC|0402|STANDARD; REACH/SVHC Compliance: Compliant; REACH/SVHC Details: SVHC List Version Jan 16, 2020; REACH/SVHC Source: REACH Declaration; REACH/SVHC Status: Unaffected; REACH/SVHC_COMPLIANCE: COMPLIANT; REACH/SVHC_DETAILS: SVHC LIST VERSION Jun 20, 2016; REACH/SVHC_SOURCE: REACH DECLARATION; REACH/SVHC_STATUS: UNAFFECTED; ROHS: Compliant; Rated Voltage: 50V; Revision: R002; RoHS Status: ROHS_COMPLIANT; Rtd Voltage: 50V; Status: Released; Texas Part Status: Under Review; Type: Capacitor; Vendor: MURATA; Vendor Part Number: GJM1555C1H1R6BB01D; Vendor Part Status: Active
C57 = CAPACITOR: CAPACITOR, CERAMIC C0G/NP0, 6.8pF, 50V, -0.1pF/+0.1pF, -55DEGC/+125DEGC, 0402, SMD; Additional Datasheet URL: https://search.murata.co.jp/Ceramy/image/img/A01X/G101/ENG/GJM1555C1H6R8BB01-01.pdf; AutoDoc File: https://notefied-dynamic-precision.com/DB/Apps/Desktop/Item/Object.aspx?id=113346; BU Name: TEXAS INSTRUMENTS NORWAY; Budget Currency: EUR; Budget Price: 0.007; Budgetary Price: 0.03466 USD; Country of Origin: Singapore; Datasheet URL: https://www.murata.com/-/media/webrenewal/support/library/catalog/products/capacitor/mlcc/c02e.ashx?la=en-gb; Datasheet URL 1: http://psearch.murata.com/capacitor/product/GRM1555C1H6R8CA01%23.pdf; Datasheet URL 2: http://search.murata.co.jp/Ceramy/image/img/w_hinm/L0005E.pdf; Dielectric Type: C0G/NP0; Lead Time: 11; Mass: 0.0016g; Max Oper Temp: +125DEGC; Max Tol: +0.25pF; Maximum Operating Temperature: +125DEGC; Maximum Tolerance: +0.1pF; Min Oper Temp: -55DEGC; Min Tol: -0.25pF; Minimum Operating Temperature: -55DEGC; Minimum Tolerance: -0.1pF; Mounting Type: SMD; NOTEfied URL: https://notefied-dynamic-precision.com/NOTEfiedWebInterface/part/show?partNumber=02-09728; PCB Package: 0402; Packing Size: 10000; Packing Type: Tape & Reel; Part Number: 02-09728; Part Type: Capacitor|CERAMIC|0402|STANDARD; REACH/SVHC Compliance: Compliant; REACH/SVHC Details: SVHC List Version Jan 16, 2020; REACH/SVHC Source: REACH Declaration; REACH/SVHC Status: Unaffected; REACH/SVHC_COMPLIANCE: COMPLIANT; REACH/SVHC_DETAILS: SVHC LIST VERSION Dec 17, 2015; REACH/SVHC_SOURCE: REACH DECLARATION; REACH/SVHC_STATUS: UNAFFECTED; ROHS: Compliant; Rated Voltage: 50V; Revision: R002; RoHS Status: ROHS_COMPLIANT; Rtd Voltage: 50V; Status: Released; Texas Part Status: Under Review; Type: Capacitor; Vendor: MURATA; Vendor Part Number: GJM1555C1H6R8BB01D; Vendor Part Status: Active; Weight: 0.0016g
C81 C91 = CAPACITOR: CAPACITOR, CERAMIC C0G/NP0, 12pF, 50V, -5%/+5%, -55DEGC/+125DEGC, 0402, SMD; Additional Datasheet URL: https://search.murata.co.jp/Ceramy/image/img/A01X/G101/ENG/GJM1555C1H120JB01-01.pdf; AutoDoc File: https://notefied-dynamic-precision.com/DB/Apps/Desktop/Item/Object.aspx?id=113345; BU Name: TEXAS INSTRUMENTS NORWAY; Budget Currency: EUR; Budget Price: 0.007; Datasheet URL: https://www.murata.com/-/media/webrenewal/support/library/catalog/products/capacitor/mlcc/c02e.ashx; Datasheet URL 1: http://psearch.murata.com/capacitor/product/GRM1555C1H120JA01%23.pdf; Datasheet URL 2: http://search.murata.co.jp/Ceramy/image/img/w_hinm/L0005E.pdf; Definied Quality: INDUSTRIAL; Dielectric Type: C0G/NP0; Esd Level: N/A; MPN: GRM1555C1H120JA01D; MPN Status: ACTIVE; MSL: 1; MTBF: N/A; MTBF Standard: N/A; Manufacturer: MURATA; Mass: 0.0016g; Max Oper Temp: +125DEGC; Max Tol: +5%; Maximum Operating Temperature: +125DEGC; Maximum Tolerance: +5%; Min Oper Temp: -55DEGC; Min Tol: -5%; Minimum Operating Temperature: -55DEGC; Minimum Tolerance: -5%; Mounting Type: SMD; NOTE Status: PREFERRED; NOTEfied URL: https://notefied-dynamic-precision.com/NOTEfiedWebInterface/part/show?partNumber=02-09704; Old Footprint: CAPC1005X60N; PCB Package: 0402; Packing Size: 10000; Packing Type: Tape & Reel; Part Number: 02-09704; Part Type: Capacitor|CERAMIC|0402|STANDARD; REACH/SVHC Compliance: Compliant; REACH/SVHC Details: SVHC List Version Jan 16, 2020; REACH/SVHC Source: REACH Declaration; REACH/SVHC Status: Unaffected; REACH/SVHC_COMPLIANCE: COMPLIANT; REACH/SVHC_DETAILS: SVHC LIST VERSION Dec 17, 2015; REACH/SVHC_SOURCE: REACH DECLARATION; REACH/SVHC_STATUS: UNAFFECTED; ROHS: Compliant; Rated Voltage: 50V; Revision: R002; RoHS Status: ROHS_COMPLIANT; Rtd Voltage: 50V; Status: Released; Texas Part Status: Under Review; Type: Capacitor; Vendor: MURATA; Vendor Part Number: GJM1555C1H120JB01D; Vendor Part Status: Active; WEIGHT: 0.0016g
C131 C221 C351 C441 C451 C481 = CAPACITOR: CAPACITOR, CERAMIC X7R, 0.1uF, 25V, -10%/+10%, -55DEGC/+125DEGC, 0402, SMD; Additional Datasheet URL: https://search.murata.co.jp/Ceramy/image/img/A01X/G101/ENG/GRM155R71E104KE14-01A.pdf; AutoDoc File: https://notefied-dynamic-precision.com/DB/Apps/Desktop/Item/Object.aspx?id=115293; BU Name: TEXAS INSTRUMENTS NORWAY; Budgetary Price: 0.00567 USD; Client Status: UNDER_REVIEW; Datasheet URL: https://www.murata.com/-/media/webrenewal/support/library/catalog/products/capacitor/mlcc/c02e.ashx?la=en-gb; Datasheet URL 1: http://psearch.en.murata.com/capacitor/product/GRM155R71E104KE14%23.pdf; Datasheet URL 2: http://search.murata.co.jp/Ceramy/image/img/w_hinm/L0005E.pdf; Dielectric Type: X7R; Lead Time: 11; LifeCycle Status: ACTIVE; MPN: GRM155R70J104KA01D; MPN Status: ACTIVE; Manufacturer: MURATA; Mass: 0.0016g; Max Oper Temp: +125DEGC; Max Tol: +10%; Maximum Operating Temperature: +125DEGC; Maximum Tolerance: +10%; Min Oper Temp: -55DEGC; Min Tol: -10%; Minimum Operating Temperature: -55DEGC; Minimum Tolerance: -10%; Mounting Type: SMD; NOTE Status: PREFERRED; NOTEfied URL: https://notefied-dynamic-precision.com/NOTEfiedWebInterface/part/show?partNumber=02-07861; Old Footprint: CAPC1005X60N,0402; PCB Package: 0402; Packing Size: 10000; Packing Type: Tape & Reel; Part Number: 02-07861; Part Type: Capacitor|CERAMIC|0402|STANDARD; REACH/SVHC Compliance: Compliant; REACH/SVHC Details: SVHC List Version Jul 7, 2017; REACH/SVHC Source: REACH Declaration; REACH/SVHC Status: Unaffected; REACH/SVHC_COMPLIANCE: COMPLIANT; REACH/SVHC_DETAILS: SVHC LIST VERSION Jun 20, 2016; REACH/SVHC_SOURCE: REACH DECLARATION; REACH/SVHC_STATUS: UNAFFECTED; ROHS: Compliant; Rated Voltage: 25V; Revision: R020; RoHS Status: ROHS_COMPLIANT; Rtd Voltage: 25V; Status: Released; Texas Part Status: Under Review; Type: Capacitor; Vendor: MURATA; Vendor Part Number: GRM155R71E104KE14D; Vendor Part Status: Active; WEIGHT: 0.0016g
C231 = CAPACITOR: CAPACITOR, CERAMIC X6S, 1uF, 16V, -10%/+10%, -55DEGC/+105DEGC, 0402, SMD; Additional Datasheet URL: https://search.murata.co.jp/Ceramy/image/img/A01X/G101/ENG/GRM155C81C105KE15-01A.pdf; AutoDoc File: https://notefied-dynamic-precision.com/DB/Apps/Desktop/Item/Object.aspx?id=115295; BU Name: TEXAS INSTRUMENTS NORWAY; Client Status: UNDER_REVIEW; Datasheet URL: https://www.murata.com/-/media/webrenewal/support/library/catalog/products/capacitor/mlcc/c02e.ashx; Datasheet URL 1: http://psearch.en.murata.com/capacitor/product/GRM155R61C105KA12%23.pdf; Datasheet URL 2: http://search.murata.co.jp/Ceramy/image/img/w_hinm/L0005E.pdf; Definied Quality: INDUSTRIAL; Dielectric Type: X6S; Esd Level: N/A; MPN: GRM155R61A105KE15D; MPN Status: ACTIVE; MSL: 1; MTBF: N/A; MTBF Standard: N/A; Manufacturer: MURATA; Mass: 0.0016g; Max Oper Temp: +85DEGC; Max Tol: +10%; Maximum Operating Temperature: +105DEGC; Maximum Tolerance: +10%; Min Oper Temp: -55DEGC; Min Tol: -10%; Minimum Operating Temperature: -55DEGC; Minimum Tolerance: -10%; Mounting Type: SMD; NOTE Status: PREFERRED; NOTEfied URL: https://notefied-dynamic-precision.com/NOTEfiedWebInterface/part/show?partNumber=02-09721; Old Footprint: CAPC1005X60N,0402; PCB Package: 0402; Packing Size: 10000; Packing Type: Tape & Reel; Part Number: 02-09721; Part Type: Capacitor|CERAMIC|0402|STANDARD; REACH/SVHC Compliance: Compliant; REACH/SVHC Details: SVHC List Version Jan 16, 2020; REACH/SVHC Source: REACH Declaration; REACH/SVHC Status: Unaffected; REACH/SVHC_COMPLIANCE: COMPLIANT; REACH/SVHC_DETAILS: SVHC LIST VERSION Jun 20, 2016; REACH/SVHC_SOURCE: REACH DECLARATION; REACH/SVHC_STATUS: UNAFFECTED; ROHS: Compliant; Rated Voltage: 16V; Revision: R002; RoHS Status: ROHS_COMPLIANT; Rtd Voltage: 16V; Status: Released; Texas Part Status: Under Review; Type: Capacitor; Vendor: MURATA; Vendor Part Number: GRM155C81C105KE15D; Vendor Part Status: Active; WEIGHT: 0.0016g
C342 = CAPACITOR: CAPACITOR, CERAMIC X7R, 0.1uF, 25V, -10%/+10%, -55DEGC/+125DEGC, 0402, SMD; Additional Datasheet URL: https://search.murata.co.jp/Ceramy/image/img/A01X/G101/ENG/GRM155R71E104KE14-01A.pdf; AutoDoc File: https://notefied-dynamic-precision.com/DB/Apps/Desktop/Item/Object.aspx?id=115293; BU Name: TEXAS INSTRUMENTS NORWAY; Budgetary Price: 0.00567 USD; Cage Code: C0151; Client Status: UNDER_REVIEW; Datasheet URL: https://www.murata.com/-/media/webrenewal/support/library/catalog/products/capacitor/mlcc/c02e.ashx?la=en-gb; Datasheet URL 1: http://psearch.en.murata.com/capacitor/product/GRM155R71E104KE14%23.pdf; Datasheet URL 2: http://search.murata.co.jp/Ceramy/image/img/w_hinm/L0005E.pdf; Definied Quality: INDUSTRIAL; Dielectric Type: X7R; Esd Level: N/A; Lead Time: 11; MPN: GRM188R71E104KA01D; MPN Status: NRND; MSL: 1; MTBF: N/A; MTBF Standard: N/A; Manufacturer: MURATA; Mass: 0.0016g; Max Oper Temp: +125DEGC; Max Tol: +10%; Maximum Operating Temperature: +125DEGC; Maximum Tolerance: +10%; Min Oper Temp: -55DEGC; Min Tol: -10%; Minimum Operating Temperature: -55DEGC; Minimum Tolerance: -10%; Mounting Type: SMD; NOTE Status: PREFERRED; NOTEfied URL: https://notefied-dynamic-precision.com/NOTEfiedWebInterface/part/show?partNumber=02-07861; Old Footprint: CAPC1608X90N,0603; PCB Package: 0402; Packing Size: 10000; Packing Type: Tape & Reel; Part Number: 02-07861; Part Type: Capacitor|CERAMIC|0402|STANDARD; REACH/SVHC Compliance: Compliant; REACH/SVHC Details: SVHC List Version Jul 7, 2017; REACH/SVHC Source: REACH Declaration; REACH/SVHC Status: Unaffected; REACH/SVHC_COMPLIANCE: COMPLIANT; REACH/SVHC_DETAILS: SVHC LIST VERSION Jun 20, 2016; REACH/SVHC_SOURCE: REACH DECLARATION; REACH/SVHC_STATUS: UNAFFECTED; ROHS: Compliant; Rated Voltage: 25V; Revision: R020; RoHS Status: ROHS_COMPLIANT; Rtd Voltage: 25V; Status: Released; Texas Part Status: Under Review; Type: Capacitor; Vendor: MURATA; Vendor Part Number: GRM155R71E104KE14D; Vendor Part Status: Active; WEIGHT: 0.0016g
C461 C471 = CAPACITOR: CAPACITOR, CERAMIC C0G/NP0, 7.5pF, 50V, -0.25pF/+0.25pF, -55DEGC/+125DEGC, 0402, SMD; Additional Datasheet URL: https://search.murata.co.jp/Ceramy/image/img/A01X/G101/ENG/GJM1555C1H7R5CB01-01.pdf; Datasheet URL: https://www.murata.com/-/media/webrenewal/support/library/catalog/products/capacitor/mlcc/c02e.ashx; Dielectric Type: C0G/NP0; Mass: 0.0016g; Maximum Operating Temperature: +125DEGC; Maximum Tolerance: +0.25pF; Minimum Operating Temperature: -55DEGC; Minimum Tolerance: -0.25pF; Mounting Type: SMD; NOTEfied URL: https://notefied-dynamic-precision.com/NOTEfiedWebInterface/part/show?partNumber=02-09718; PCB Package: 0402; Packing Size: 10000; Packing Type: Tape & Reel; Part Number: 02-09718; Part Type: Capacitor|CERAMIC|0402|STANDARD; REACH/SVHC Compliance: Compliant; REACH/SVHC Details: SVHC List Version Jan 16, 2020; REACH/SVHC Source: REACH Declaration; REACH/SVHC Status: Unaffected; ROHS: Compliant; Rated Voltage: 50V; Revision: R002; Status: Released; Texas Part Status: Under Review; Type: Capacitor; Vendor: MURATA; Vendor Part Number: GJM1555C1H7R5CB01D; Vendor Part Status: Active
FL1 = FILTER_2PIN: FILTER, EMI, FERRITE BEAD, 1500@100MHz, -25%/+25%, -55DEGC/+125DEGC, 0603, SMD; ALT_SYMBOLS: FIL_BLM18HE152SN1DL,FIL_BLM18HE152SN1DM; Additional Datasheet URL: https://www.murata.com/en-eu/products/productdata/8796741599262/ENFA0004.pdf?1531144803000; AutoDoc File: https://notefied-dynamic-precision.com/DB/Apps/Desktop/Item/Object.aspx?id=85575; BU Name: DYNAMIC PRECISION GDANSK; Budget Currency: EUR; Budget Price: 0.065; Budgetary Price: 0.07 EUR; CLASS: IC; Client Status: UNDER_REVIEW; Country of Origin: Japan,Singapore,Thailand; Datasheet URL: https://www.murata.com/~/media/webrenewal/support/library/catalog/products/emc/emifil/c31e.ashx; Datasheet URL 1: http://search.murata.co.jp/Ceramy/image/img/PDF/ENG/L0110S0101BLM18H.pdf; Datasheet URL 2: http://search.murata.co.jp/Ceramy/image/img/w_hinm/L0110E.pdf; Frequency: 100MHz; Impedance: 1500; Inductance: N/A; Lead Time: 8; MPN: BLM18HE152SN1D; MPN Status: ACTIVE; Manufacturer: MURATA; Mass: 0.006g; Max Oper Temp: +125DEGC; Max Tol: +25%; Maximum Operating Temperature: +125DEGC; Maximum Tolerance: +25%; Min Oper Temp: -55DEGC; Min Tol: -25%; Minimum Operating Temperature: -55DEGC; Minimum Tolerance: -25%; Mounting Type: SMD; NOTE Status: PREFERRED; NOTEfied URL: https://notefied-dynamic-precision.com/NOTEfiedWebInterface/part/show?partNumber=04-00470; PCB Package: 0603; Packing Size: 4000; Packing Type: Tape & Reel; Part Number: 04-00470; Part Type: Filter|EMI|FERRITE BEAD|0603; REACH/SVHC Compliance: Compliant; REACH/SVHC Details: SVHC List Version Jul 7, 2017; REACH/SVHC Source: REACH Declaration; REACH/SVHC Status: Unaffected; REACH/SVHC_COMPLIANCE: COMPLIANT; REACH/SVHC_DETAILS: SVHC LIST VERSION Dec 17, 2015; REACH/SVHC_SOURCE: REACH DECLARATION; REACH/SVHC_STATUS: UNAFFECTED; ROHS: Compliant; Rated Current: 0.5A; Rated Voltage: N/A; Revision: R021; RoHS Status: ROHS_COMPLIANT; Rtd Current: 0.5A; Rtd Voltage: N/A; Status: Released; Texas Part Status: Under Review; Type: Filter; Vendor: MURATA; Vendor Part Number: BLM18HE152SN1D; Vendor Part Status: Active; WEIGHT: 0.006g
J1-J3 = CONN_COAX_1+4: CONNECTOR, COAX, RF, FEMALE, STRAIGHT, 1 PIN, SMD; ALT_SYMBOLS: HUSTSAN_SMA10V21TGGL,HUSTSAN_SMA10V21TGGM; Additional Datasheet URL: http://www.hustsan.com.tw/cgi-bin/productfn/pdt_detail_lst.pl?ProdID=143; AutoDoc File: https://notefied-dynamic-precision.com/DB/Apps/Desktop/Item/Object.aspx?id=84956; BU Name: DYNAMIC PRECISION GDANSK; Budget Currency: N/A; Budget Price: N/A; CLASS: IO; Client Status: UNDER_REVIEW; Country of Origin: Taiwan; Datasheet URL: http://www.hustsan.com.tw/uploaddir/product/SMA-10V21.pdf; Datasheet URL 1: http://www.hustsan.com.tw/uploaddir/product/SMA-10V21.pdf; Datasheet URL 2: http://www.hustsan.com.tw/cgi-bin/productfn/pdt_detail_lst.pl?ProdID=143; FPLIST: HUSTSAN_SMA10V21TGGAN,HUSTSAN_SMA10V21TGGN; MPN Status: ACTIVE; MSL: N/A; Manufacturer: HUS-TSAN; Mass: N/A; Mounting Type: SMD; NOTE Status: PREFERRED; NOTEfied URL: https://notefied-dynamic-precision.com/NOTEfiedWebInterface/part/show?partNumber=06-02188; No Of Pos: 1; Number of Positions: 1; Old Footprint: HUSTSAN_SMA10V21TGGAN,HUSTSAN_SMA10V21TGGN; Packing Size: 350; Packing Type: Tape & Reel; Part Number: 06-02188; Part Type: Connector|COAX|RF; REACH/SVHC Compliance: Compliant; REACH/SVHC Details: SVHC List Version Jun 20, 2016; REACH/SVHC Source: REACH Declaration; REACH/SVHC Status: Unaffected; ROHS: Compliant; Revision: R021; RoHS Status: ROHS_COMPLIANT; Status: Released; Texas Part Status: Under Review; Type: Connector; Vendor: HUS-TSAN; Vendor Part Status: Active; WEIGHT: N/A
L11 L51 = INDUCTOR_HOR_1_2: INDUCTOR, RF, CHIP, NON-MAGNETIC CORE, 15nH, -5%/+5%, 0.3A, -55DEGC/+125DEGC, 0402, SMD; ALT_SYMBOLS: INDC1005X60C2L,INDC1005X60C2M; Additional Datasheet URL: https://search.murata.co.jp/Ceramy/image/img/P02/JELF243B-0010.pdf; AutoDoc File: https://notefied-dynamic-precision.com/DB/Apps/Desktop/Item/Object.aspx?id=87741; BU Name: TEXAS INSTRUMENTS NORWAY; Budget Currency: EUR; Budget Price: 0.03; Budgetary Price: 0.01872 USD; Client Status: UNDER_REVIEW; Core Material: NON-MAGNETIC; Country of Origin: Japan,Singapore; Datasheet URL: https://www.murata.com/-/media/webrenewal/support/library/catalog/products/inductor/chip/o05e.ashx?la=en-gb; Datasheet URL 1: http://psearch.murata.com/inductor/product/LQG15HS15NJ02%23.pdf; Datasheet URL 2: http://www.murata.com/~/media/webrenewal/support/library/catalog/products/inductor/chip/o05e.ashx; FPLIST: INDC1005X60C2N,INDC1005X60D2N; Frequency: 2.5GHz; Lead Time: 8; Mass: 0.001g; Max Oper Temp: +125DEGC; Max Tol: +5%; Maximum Operating Temperature: +125DEGC; Maximum Tolerance: +5%; Min Oper Temp: -55DEGC; Min Tol: -5%; Minimum Operating Temperature: -55DEGC; Minimum Tolerance: -5%; Mounting Type: SMD; NOTEfied URL: https://notefied-dynamic-precision.com/NOTEfiedWebInterface/part/show?partNumber=03-06637; PCB Package: 0402; Packing Size: 10000; Packing Type: Tape & Reel; Part Number: 03-06637; Part Type: Inductor|RF|CHIP|0402; REACH/SVHC Compliance: Compliant; REACH/SVHC Details: SVHC List Version Jul 7, 2017; REACH/SVHC Source: REACH Declaration; REACH/SVHC Status: Unaffected; REACH/SVHC_COMPLIANCE: COMPLIANT; REACH/SVHC_DETAILS: SVHC LIST VERSION Dec 17, 2015; REACH/SVHC_SOURCE: REACH DECLARATION; REACH/SVHC_STATUS: UNAFFECTED; ROHS: Compliant; Resistance: 0.32; Revision: R024; RoHS Status: ROHS_COMPLIANT; Rtd Current: 0.3A; Status: Released; Texas Part Status: Under Review; Type: Inductor; Vendor: MURATA; Vendor Part Number: LQG15HS15NJ02D; Vendor Part Status: Active; Weight: 0.001g
L12 L21 = INDUCTOR_HOR_1_2: INDUCTOR, RF, CHIP, NON-MAGNETIC CORE, 2.4nH, -0.3nH/+0.3nH, 0.3A, -55DEGC/+125DEGC, 0402, SMD; Additional Datasheet URL: https://search.murata.co.jp/Ceramy/image/img/P02/JELF243B-0010.pdf; AutoDoc File: https://notefied-dynamic-precision.com/DB/Apps/Desktop/Item/Object.aspx?id=113363; BU Name: TEXAS INSTRUMENTS NORWAY; Budget Currency: EUR; Budget Price: 0.031; Budgetary Price: 0.01872 USD; Client Status: UNDER_REVIEW; Core Material: NON-MAGNETIC; Country of Origin: Japan,Singapore; Datasheet URL: https://www.murata.com/-/media/webrenewal/support/library/catalog/products/inductor/chip/o05e.ashx?la=en-gb; Datasheet URL 1: http://psearch.murata.com/inductor/product/LQG15HS2N4S02%23.pdf; Datasheet URL 2: http://www.murata.com/~/media/webrenewal/support/library/catalog/products/inductor/chip/o05e.ashx; Exclusive for Customers: TEXAS INSTRUMENTS NORWAY; Frequency: 6GHz; Lead Time: 8; Mass: 0.001g; Max Oper Temp: +125DEGC; Max Tol: +0.3nH; Maximum Operating Temperature: +125DEGC; Maximum Tolerance: +0.3nH; Min Oper Temp: -55DEGC; Min Tol: -0.3nH; Minimum Operating Temperature: -55DEGC; Minimum Tolerance: -0.3nH; Mounting Type: SMD; NOTEfied URL: https://notefied-dynamic-precision.com/NOTEfiedWebInterface/part/show?partNumber=03-07526; Notes: Standard item: Duplicate Reason: custom footprint for TEXAS INSTRUMENTS NORWAY.; PCB Package: 0402; Packing Size: 10000; Packing Type: Tape & Reel; Part Number: 03-07526; Part Type: Inductor|RF|CHIP|0402; REACH/SVHC Compliance: Compliant; REACH/SVHC Details: SVHC List Version Jul 7, 2017; REACH/SVHC Source: REACH Declaration; REACH/SVHC Status: Unaffected; REACH/SVHC_COMPLIANCE: COMPLIANT; REACH/SVHC_DETAILS: SVHC LIST VERSION Dec 17, 2015; REACH/SVHC_SOURCE: REACH DECLARATION; REACH/SVHC_STATUS: UNAFFECTED; ROHS: Compliant; Revision: R024; RoHS Status: ROHS_COMPLIANT; Rtd Current: 0.3A; Status: Released; Texas Part Status: Under Review; Type: Inductor; Vendor: MURATA; Vendor Part Number: LQG15HS2N4S02D; Vendor Part Status: Active; Weight: 0.001g
L13 = INDUCTOR_HOR_1_2: INDUCTOR, RF, CHIP, NON-MAGNETIC CORE, 1.5nH, -0.3nH/+0.3nH, 0.3A, -55DEGC/+125DEGC, 0402, SMD; Additional Datasheet URL: https://search.murata.co.jp/Ceramy/image/img/P02/JELF243B-0010.pdf; AutoDoc File: https://notefied-dynamic-precision.com/DB/Apps/Desktop/Item/Object.aspx?id=113368; BU Name: TEXAS INSTRUMENTS NORWAY; Budget Currency: EUR; Budget Price: 0.031; Budgetary Price: 0.01872 USD; Client Status: UNDER_REVIEW; Core Material: NON-MAGNETIC; Country of Origin: Japan,Singapore; Datasheet URL: https://www.murata.com/-/media/webrenewal/support/library/catalog/products/inductor/chip/o05e.ashx?la=en-gb; Datasheet URL 1: http://psearch.murata.com/inductor/product/LQG15HS1N5S02%23.pdf; Datasheet URL 2: http://www.murata.com/~/media/webrenewal/support/library/catalog/products/inductor/chip/o05e.ashx; Exclusive for Customers: TEXAS INSTRUMENTS NORWAY; Frequency: 6GHz; Lead Time: 8; Mass: 0.001g; Max Oper Temp: +125DEGC; Max Tol: +0.3nH; Maximum Operating Temperature: +125DEGC; Maximum Tolerance: +0.3nH; Min Oper Temp: -55DEGC; Min Tol: -0.3nH; Minimum Operating Temperature: -55DEGC; Minimum Tolerance: -0.3nH; Mounting Type: SMD; NOTEfied URL: https://notefied-dynamic-precision.com/NOTEfiedWebInterface/part/show?partNumber=03-07531; Notes: Standard item: Duplicate Reason: custom footprint for TEXAS INSTRUMENTS NORWAY.; PCB Package: 0402; Packing Size: 10000; Packing Type: Tape & Reel; Part Number: 03-07531; Part Type: Inductor|RF|CHIP|0402; REACH/SVHC Compliance: Compliant; REACH/SVHC Details: SVHC List Version Jul 7, 2017; REACH/SVHC Source: REACH Declaration; REACH/SVHC Status: Unaffected; REACH/SVHC_COMPLIANCE: COMPLIANT; REACH/SVHC_DETAILS: SVHC List Version Jun 20, 2016; REACH/SVHC_SOURCE: REACH DECLARATION; REACH/SVHC_STATUS: UNAFFECTED; ROHS: Compliant; Resistance: 0.1; Revision: R023; RoHS Status: ROHS_COMPLIANT; Rtd Current: 0.3A; Status: Released; Texas Part Status: Under Review; Type: Inductor; Vendor: MURATA; Vendor Part Number: LQG15HS1N5S02D; Vendor Part Status: Active; Weight: 0.001g
